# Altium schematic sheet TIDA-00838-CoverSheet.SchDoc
size 431 x 279 mm; Date: Not shown in title block; ApprovedBy: Not shown in title block; CheckedBy: Not shown in title block; Author: Not shown in title block; CompanyName: Not shown in title block; Engineer: Not shown in title block; Organization: Not shown in title block; Address1: Not shown in title block; Address2: Not shown in title block; Address3: Not shown in title block; Address4: Not shown in title block; DocumentNumber: 1; Revision: Use project parameter SCH_Rev; SheetNumber: 1; SheetTotal: 3; PageSetup: Record=PageOptions¦CenterHorizontal=True¦CenterVertical=True¦PrintScale=1.00¦XCorrection=1.00¦YCorrection=1.00¦PrintKind=0¦BorderSize=5000000¦LeftOffset=0¦BottomOffset=0¦Orientation=2¦PaperLength=1000¦PaperWidth=1000¦Scale=100¦PaperSource=15¦PrintQuality=600¦MediaType=1¦DitherType=10¦PaperKind=Letter¦PrintScaleMode=1
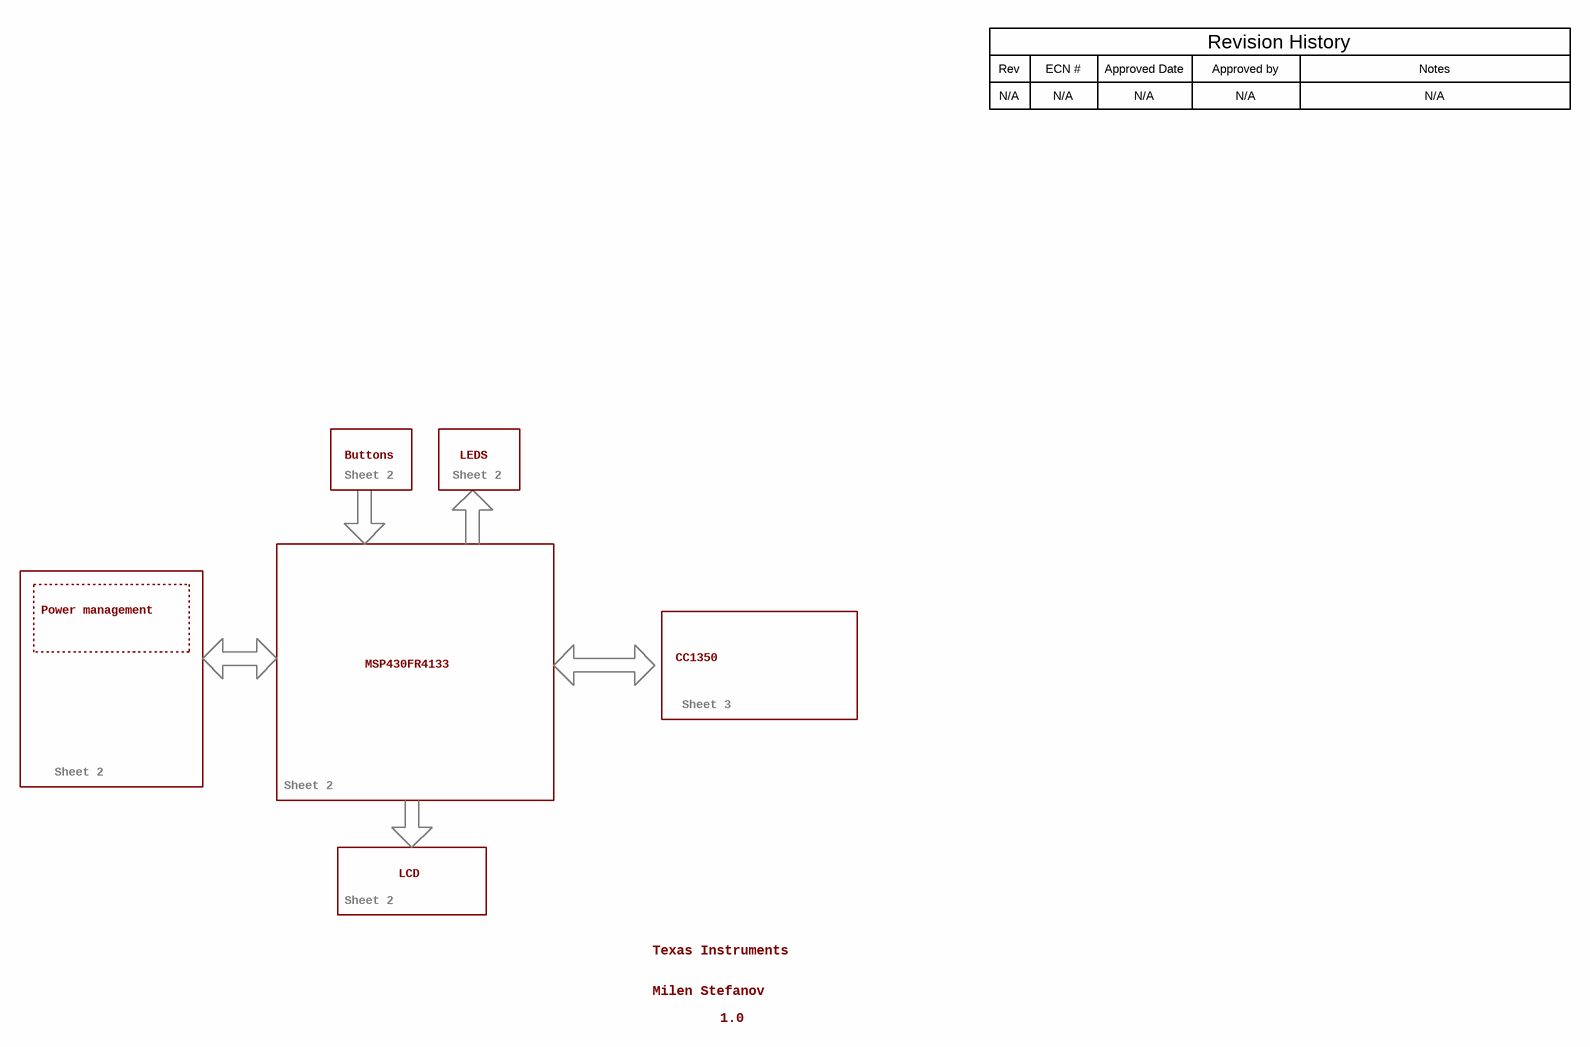
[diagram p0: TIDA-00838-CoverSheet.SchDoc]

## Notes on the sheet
- Rev
- N/A
- ECN #
- Approved Date
- Approved by
- Revision History
- Notes
- Buttons
- Sheet 2
- LEDS
- Power management
- MSP430FR4133
- CC1350
- Sheet 3
- LCD
- Texas Instruments
- Milen Stefanov
- 1.0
